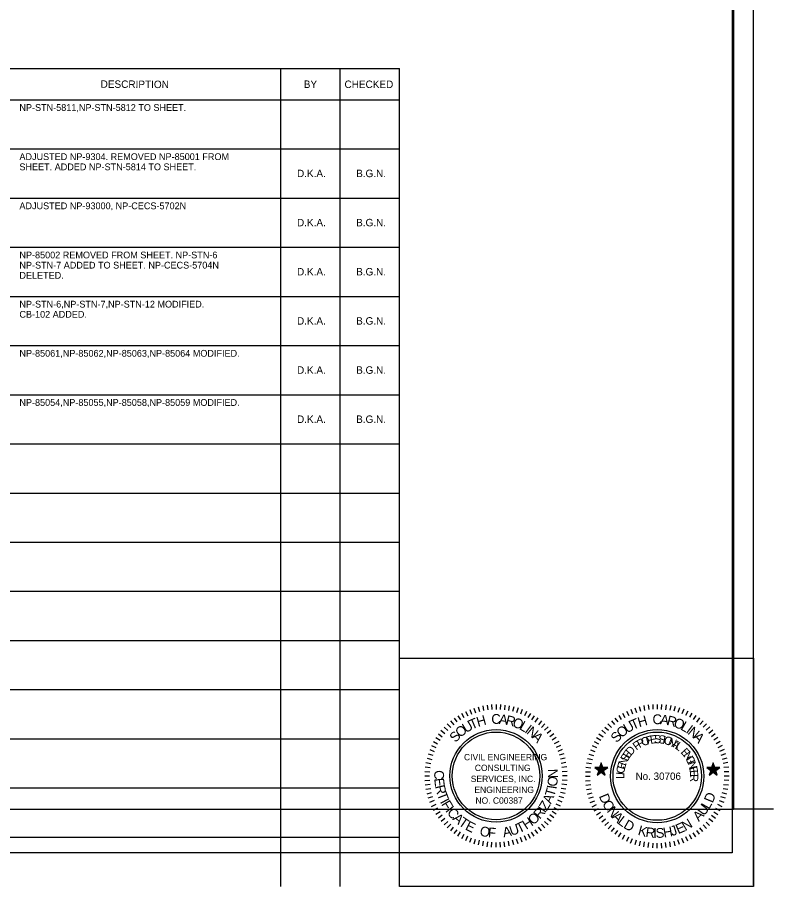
# Model space of a CAD drawing. Extents: x 260980 to 262786, y 322332 to 323393.
# Drawn here: x 262340 to 262786, y 322332 to 322845 of the extents above; entities that cross this region are included whole.
import ezdxf

# ---------------------------------------------------------------- set-up
doc = ezdxf.new("R2010")
doc.units = 0
for name, color, linetype in [('Level 1', 7, 'Continuous'), ('Level 2', 7, 'Continuous'), ('Level 23', 7, 'Continuous'), ('Level 3', 7, 'Continuous'), ('Level 5', 7, 'Continuous'), ('RD_SHT_SEAL_KA', 7, 'Continuous'), ('RD_SHT_TX', 7, 'Continuous')]:
    doc.layers.add(name, color=color, linetype=linetype)

msp = doc.modelspace()

# ---------------------------------------------------------------- linework, layer by layer
at = {"layer": 'Level 1'}
msp.add_lwpolyline([(262565.22, 322466.63), (262774.17, 322466.63), (262774.17, 322331.93), (262565.22, 322331.93)], close=True, dxfattribs=at)
at = {"layer": 'Level 2'}
msp.add_line((262761.95, 322377.79), (262785.98, 322377.79), dxfattribs=at)
at = {"layer": 'Level 23'}
msp.add_lwpolyline([(261111.06, 323336.45), (262761.54, 323336.45), (262761.54, 322351.79), (261111.06, 322351.79)], close=True, dxfattribs=at)
msp.add_lwpolyline([(261111.06, 323336.45), (262761.54, 323336.45), (262761.54, 322351.79), (261111.06, 322351.79)], close=True, dxfattribs=at)
at = {"layer": 'Level 3'}
msp.add_line((262774.17, 322332.83), (262774.17, 323381.93), dxfattribs=at)
at = {"layer": 'Level 5'}
msp.add_lwpolyline([(261111.06, 323310.45), (262762.33, 323310.45), (262762.33, 322377.34), (261111.06, 322377.34)], close=True, dxfattribs=at)
at = {"layer": 'RD_SHT_SEAL_KA'}
for p, q in [((262604.29, 322435.3), (262605.54, 322432.74)), ((262606.76, 322436.43), (262607.81, 322433.69)), ((262609.18, 322437.25), (262610.09, 322434.5)), ((262611.77, 322438.02), (262612.38, 322435.23)), ((262614.37, 322438.65), (262614.85, 322435.76)), ((262617.01, 322438.98), (262617.36, 322436.19)), ((262619.61, 322439.34), (262619.76, 322436.38)), ((262622.25, 322439.41), (262622.24, 322436.5)), ((262624.87, 322439.29), (262624.67, 322436.4)), ((262627.44, 322439.02), (262627.12, 322436.22)), ((262630.06, 322438.63), (262629.58, 322435.89)), ((262632.67, 322437.99), (262631.94, 322435.18)), ((262635.18, 322437.3), (262634.33, 322434.51)), ((262637.64, 322436.38), (262636.7, 322433.73)), ((262640.12, 322435.31), (262638.92, 322432.67)), ((262699.25, 322435.47), (262700.5, 322432.88)), ((262701.68, 322436.55), (262702.77, 322433.79)), ((262704.17, 322437.41), (262705.14, 322434.71)), ((262706.71, 322438.17), (262707.46, 322435.36)), ((262709.41, 322438.76), (262709.89, 322435.85)), ((262712.05, 322439.14), (262712.38, 322436.33)), ((262714.65, 322439.41), (262714.81, 322436.55)), ((262717.35, 322439.46), (262717.29, 322436.66)), ((262719.88, 322439.41), (262719.72, 322436.44)), ((262722.64, 322439.19), (262722.26, 322436.28)), ((262725.28, 322438.76), (262724.74, 322435.95)), ((262727.88, 322438.17), (262727.12, 322435.36)), ((262730.41, 322437.46), (262729.55, 322434.66)), ((262732.95, 322436.55), (262731.87, 322433.85)), ((262735.33, 322435.47), (262734.08, 322432.82)), ((262597.49, 322431.32), (262599.11, 322429.06)), ((262599.73, 322432.75), (262601.21, 322430.41)), ((262601.9, 322434.18), (262603.29, 322431.64)), ((262642.46, 322434.15), (262641.02, 322431.7)), ((262644.8, 322432.73), (262643.2, 322430.33)), ((262646.9, 322431.43), (262645.19, 322428.98)), ((262692.34, 322431.36), (262694.07, 322429.04)), ((262694.61, 322432.88), (262696.12, 322430.5)), ((262696.83, 322434.28), (262698.28, 322431.69)), ((262737.7, 322434.28), (262736.35, 322431.8)), ((262740.08, 322432.88), (262738.51, 322430.45)), ((262742.24, 322431.42), (262740.57, 322428.99)), ((262591.59, 322426.04), (262593.73, 322424.11)), ((262593.36, 322427.97), (262595.45, 322425.89)), ((262595.44, 322429.8), (262597.23, 322427.41)), ((262648.98, 322429.68), (262647.25, 322427.45)), ((262650.99, 322427.92), (262649.01, 322425.88)), ((262652.96, 322426.12), (262650.75, 322424.13)), ((262686.4, 322426.02), (262688.51, 322424.13)), ((262688.18, 322428.01), (262690.29, 322425.86)), ((262690.24, 322429.8), (262692.07, 322427.53)), ((262744.35, 322429.8), (262742.51, 322427.59)), ((262746.34, 322428.01), (262744.45, 322425.91)), ((262748.29, 322426.13), (262746.13, 322424.13)), ((262586.67, 322419.87), (262589.17, 322418.32)), ((262588.19, 322422), (262590.45, 322420.31)), ((262589.71, 322424.13), (262592.03, 322422.26)), ((262654.59, 322424.12), (262652.41, 322422.25)), ((262656.24, 322421.98), (262653.88, 322420.31)), ((262682.95, 322422.02), (262685.38, 322420.29)), ((262684.57, 322424.13), (262686.83, 322422.29)), ((262750.02, 322424.13), (262747.8, 322422.29)), ((262751.58, 322422.02), (262749.31, 322420.35)), ((262584.16, 322415.2), (262586.73, 322413.99)), ((262585.4, 322417.48), (262587.76, 322416.17)), ((262657.74, 322419.83), (262655.32, 322418.33)), ((262659.17, 322417.58), (262656.56, 322416.1)), ((262660.22, 322415.18), (262657.76, 322413.98)), ((262678.9, 322415.16), (262681.49, 322413.92)), ((262680.14, 322417.49), (262682.68, 322416.14)), ((262681.49, 322419.86), (262683.97, 322418.24)), ((262753.15, 322419.81), (262750.72, 322418.3)), ((262754.5, 322417.49), (262752.01, 322416.08)), ((262755.63, 322415.16), (262753.09, 322413.87)), ((262582.17, 322410.26), (262585, 322409.38)), ((262583.12, 322412.76), (262585.72, 322411.67)), ((262661.26, 322412.78), (262658.64, 322411.71)), ((262662.24, 322410.3), (262659.49, 322409.39)), ((262676.95, 322410.14), (262679.71, 322409.28)), ((262677.87, 322412.68), (262680.57, 322411.6)), ((262756.77, 322412.74), (262754.07, 322411.65)), ((262757.68, 322410.2), (262754.93, 322409.28)), ((262580.88, 322405.11), (262583.73, 322404.61)), ((262581.49, 322407.68), (262584.26, 322406.91)), ((262662.98, 322407.67), (262660.15, 322407.09)), ((262663.48, 322405.16), (262660.69, 322404.55)), ((262675.66, 322405.01), (262678.52, 322404.53)), ((262676.2, 322407.6), (262679.06, 322406.9)), ((262758.44, 322407.66), (262755.58, 322406.96)), ((262759.03, 322405.06), (262756.12, 322404.47)), ((262580.27, 322399.82), (262583.12, 322399.65)), ((262580.46, 322402.52), (262583.38, 322402.1)), ((262664.03, 322402.55), (262661.03, 322402.17)), ((262664.22, 322399.89), (262661.3, 322399.71)), ((262675.01, 322399.72), (262677.87, 322399.56)), ((262675.23, 322402.36), (262678.09, 322402.04)), ((262759.47, 322402.36), (262756.55, 322402.1)), ((262759.63, 322399.72), (262756.77, 322399.56)), ((262580.26, 322394.6), (262583.13, 322394.81)), ((262580.29, 322397.29), (262583.05, 322397.26)), ((262664.21, 322394.6), (262661.32, 322394.8)), ((262664.2, 322397.32), (262661.45, 322397.27)), ((262674.95, 322397.07), (262677.82, 322397.07)), ((262674.95, 322394.43), (262677.82, 322394.59)), ((262759.63, 322394.48), (262756.77, 322394.64)), ((262759.73, 322397.07), (262756.87, 322397.13)), ((262580.5, 322392.02), (262583.37, 322392.31)), ((262580.83, 322389.38), (262583.68, 322389.89)), ((262663.49, 322389.33), (262660.66, 322389.87)), ((262663.97, 322392), (262661.03, 322392.3)), ((262675.23, 322391.73), (262678.14, 322392.16)), ((262675.6, 322389.14), (262678.41, 322389.62)), ((262759.03, 322389.14), (262756.12, 322389.68)), ((262759.36, 322391.78), (262756.5, 322392.05)), ((262581.5, 322386.75), (262584.2, 322387.49)), ((262582.25, 322384.31), (262584.94, 322385.13)), ((262662.22, 322384.29), (262659.43, 322385.14)), ((262662.98, 322386.81), (262660.17, 322387.54)), ((262676.25, 322386.49), (262679, 322387.19)), ((262677.01, 322384.01), (262679.71, 322384.87)), ((262757.63, 322384.01), (262754.93, 322384.87)), ((262758.44, 322386.54), (262755.58, 322387.3)), ((262583.09, 322381.73), (262585.82, 322382.86)), ((262584.15, 322379.26), (262586.85, 322380.6)), ((262660.26, 322379.39), (262657.73, 322380.57)), ((262661.3, 322381.83), (262658.64, 322382.84)), ((262677.82, 322381.47), (262680.57, 322382.49)), ((262678.95, 322378.99), (262681.54, 322380.28)), ((262755.68, 322378.99), (262753.09, 322380.28)), ((262756.77, 322381.52), (262754.01, 322382.55)), ((262585.41, 322376.96), (262587.83, 322378.45)), ((262586.73, 322374.74), (262589.18, 322376.27)), ((262588.24, 322372.43), (262590.44, 322374.23)), ((262656.22, 322372.41), (262653.91, 322374.2)), ((262657.77, 322374.58), (262655.26, 322376.2)), ((262659.04, 322376.97), (262656.48, 322378.36)), ((262680.08, 322376.61), (262682.68, 322378.06)), ((262681.54, 322374.34), (262683.87, 322375.85)), ((262683, 322372.13), (262685.32, 322373.85)), ((262751.63, 322372.13), (262749.31, 322373.8)), ((262753.15, 322374.29), (262750.72, 322375.8)), ((262754.5, 322376.66), (262751.96, 322378.01)), ((262589.76, 322370.46), (262591.99, 322372.23)), ((262591.57, 322368.45), (262593.75, 322370.4)), ((262593.44, 322366.6), (262595.45, 322368.68)), ((262651.03, 322366.58), (262648.97, 322368.71)), ((262652.88, 322368.45), (262650.81, 322370.39)), ((262654.68, 322370.43), (262652.41, 322372.19)), ((262684.62, 322370.07), (262686.89, 322371.86)), ((262686.4, 322368.02), (262688.51, 322370.02)), ((262748.23, 322368.02), (262746.18, 322370.02)), ((262750.07, 322370.07), (262747.8, 322371.91)), ((262595.46, 322364.77), (262597.19, 322367)), ((262597.51, 322363.24), (262599.2, 322365.5)), ((262599.64, 322361.72), (262601.2, 322364.15)), ((262644.7, 322361.77), (262643.22, 322364.11)), ((262646.9, 322363.23), (262645.25, 322365.45)), ((262648.95, 322364.76), (262647.25, 322367)), ((262688.35, 322366.08), (262690.24, 322368.24)), ((262690.29, 322364.4), (262692.07, 322366.56)), ((262692.4, 322362.79), (262694.13, 322365.05)), ((262694.56, 322361.22), (262696.12, 322363.7)), ((262740.03, 322361.22), (262738.51, 322363.65)), ((262742.29, 322362.79), (262740.62, 322365.11)), ((262744.29, 322364.35), (262742.51, 322366.56)), ((262746.4, 322366.13), (262744.4, 322368.29)), ((262601.97, 322360.37), (262603.34, 322362.81)), ((262604.32, 322359.14), (262605.51, 322361.85)), ((262606.72, 322358.13), (262607.81, 322360.73)), ((262609.22, 322357.18), (262610.07, 322359.97)), ((262611.8, 322356.5), (262612.38, 322359.29)), ((262614.33, 322355.92), (262614.83, 322358.77)), ((262616.93, 322355.42), (262617.34, 322358.34)), ((262627.43, 322355.47), (262627.1, 322358.37)), ((262630.02, 322355.91), (262629.59, 322358.68)), ((262632.66, 322356.5), (262631.98, 322359.28)), ((262635.18, 322357.19), (262634.32, 322359.91)), ((262637.71, 322358.14), (262636.63, 322360.83)), ((262640.18, 322359.19), (262638.92, 322361.83)), ((262642.49, 322360.37), (262641.14, 322362.81)), ((262696.88, 322359.92), (262698.28, 322362.41)), ((262699.31, 322358.68), (262700.5, 322361.33)), ((262701.63, 322357.6), (262702.82, 322360.3)), ((262704.22, 322356.74), (262705.03, 322359.49)), ((262706.76, 322355.93), (262707.41, 322358.79)), ((262727.88, 322355.98), (262727.23, 322358.79)), ((262730.41, 322356.74), (262729.55, 322359.44)), ((262732.95, 322357.6), (262731.87, 322360.3)), ((262735.43, 322358.74), (262734.19, 322361.33)), ((262737.7, 322359.92), (262736.35, 322362.41)), ((262619.63, 322355.24), (262619.79, 322358.17)), ((262622.25, 322355.2), (262622.23, 322357.99)), ((262624.92, 322355.23), (262624.74, 322358.15)), ((262709.35, 322355.39), (262709.89, 322358.3)), ((262712, 322355.01), (262712.38, 322357.87)), ((262714.7, 322354.74), (262714.86, 322357.6)), ((262717.35, 322354.69), (262717.35, 322357.55)), ((262719.99, 322354.63), (262719.83, 322357.65)), ((262722.58, 322355.01), (262722.26, 322357.87)), ((262725.23, 322355.39), (262724.74, 322358.25))]:
    msp.add_line(p, q, dxfattribs=at)
for points in [[(262684.24, 322405.01), (262683.33, 322402.15), (262680.41, 322402.15), (262682.78, 322400.37), (262681.81, 322397.67), (262684.3, 322399.4), (262686.62, 322397.67), (262685.7, 322400.42), (262688.08, 322402.2), (262685.16, 322402.2)], [(262684.19, 322404.58), (262683.43, 322402.1), (262680.73, 322402.1), (262682.84, 322400.48), (262682.08, 322397.94), (262684.19, 322399.56), (262686.35, 322397.94), (262685.54, 322400.53), (262687.75, 322402.04), (262685.11, 322402.1)], [(262750.39, 322405.01), (262749.42, 322402.2), (262746.56, 322402.15), (262748.93, 322400.42), (262747.96, 322397.61), (262750.39, 322399.4), (262752.77, 322397.61), (262751.8, 322400.42), (262754.23, 322402.2), (262751.26, 322402.2)], [(262750.34, 322404.64), (262749.53, 322402.1), (262746.88, 322402.04), (262749.1, 322400.42), (262748.29, 322397.94), (262750.39, 322399.45), (262752.55, 322397.94), (262751.74, 322400.48), (262753.9, 322402.1), (262751.2, 322402.04)], [(262684.3, 322404.2), (262683.43, 322401.94), (262681.11, 322401.94), (262683.05, 322400.53), (262682.35, 322398.26), (262684.24, 322399.66), (262686.19, 322398.21), (262685.38, 322400.59), (262687.38, 322401.88), (262685, 322401.94)], [(262684.3, 322403.82), (262683.54, 322401.83), (262681.49, 322401.77), (262683.22, 322400.59), (262682.57, 322398.59), (262684.19, 322399.83), (262685.97, 322398.59), (262685.38, 322400.59), (262687, 322401.88), (262684.89, 322401.77)], [(262684.24, 322403.45), (262683.7, 322401.72), (262681.87, 322401.66), (262683.33, 322400.64), (262682.73, 322398.86), (262684.24, 322399.99), (262685.75, 322398.86), (262685.16, 322400.64), (262686.57, 322401.72), (262684.89, 322401.72)], [(262684.24, 322403.07), (262683.81, 322401.56), (262682.25, 322401.61), (262683.49, 322400.69), (262683, 322399.24), (262684.3, 322400.15), (262685.54, 322399.18), (262685, 322400.69), (262686.3, 322401.5), (262684.73, 322401.56)], [(262684.24, 322402.64), (262683.87, 322401.5), (262682.62, 322401.34), (262683.65, 322400.75), (262683.27, 322399.56), (262684.19, 322400.26), (262685.32, 322399.5), (262684.95, 322400.75), (262685.86, 322401.45), (262684.62, 322401.45)], [(262684.24, 322402.26), (262683.97, 322401.34), (262683, 322401.34), (262683.81, 322400.8), (262683.49, 322399.88), (262684.24, 322400.37), (262685.05, 322399.83), (262684.78, 322400.75), (262685.54, 322401.29), (262684.51, 322401.39)], [(262684.24, 322401.83), (262684.03, 322401.23), (262683.33, 322401.23), (262683.87, 322400.8), (262683.76, 322400.21), (262684.3, 322400.59), (262684.73, 322400.15), (262684.62, 322400.8), (262685.16, 322401.18), (262684.46, 322401.23)], [(262684.3, 322401.5), (262684.08, 322401.12), (262683.76, 322401.12), (262684.08, 322400.85), (262683.92, 322400.48), (262684.3, 322400.75), (262684.51, 322400.48), (262684.4, 322400.91), (262684.73, 322401.07), (262684.4, 322401.07)], [(262684.3, 322401.07), (262684.24, 322400.91), (262684.03, 322400.96), (262684.19, 322400.96), (262684.13, 322400.8), (262684.24, 322400.8), (262684.3, 322400.8), (262684.3, 322400.91), (262684.46, 322401.01), (262684.3, 322401.01)], [(262750.39, 322404.2), (262749.69, 322401.88), (262747.26, 322401.94), (262749.2, 322400.53), (262748.5, 322398.21), (262750.39, 322399.66), (262752.34, 322398.26), (262751.58, 322400.48), (262753.53, 322401.99), (262751.15, 322401.94)], [(262750.34, 322403.82), (262749.75, 322401.77), (262747.64, 322401.77), (262749.42, 322400.59), (262748.61, 322398.64), (262750.39, 322399.83), (262752.07, 322398.64), (262751.42, 322400.59), (262753.15, 322401.83), (262751.04, 322401.83)], [(262750.34, 322403.39), (262749.8, 322401.66), (262747.96, 322401.72), (262749.42, 322400.69), (262748.93, 322398.86), (262750.34, 322399.94), (262751.8, 322398.91), (262751.31, 322400.59), (262752.82, 322401.66), (262750.93, 322401.72)], [(262750.45, 322403.01), (262749.91, 322401.61), (262748.34, 322401.61), (262749.64, 322400.75), (262749.1, 322399.18), (262750.39, 322400.1), (262751.58, 322399.24), (262751.2, 322400.64), (262752.34, 322401.56), (262750.88, 322401.61)], [(262750.39, 322402.64), (262749.96, 322401.5), (262748.72, 322401.45), (262749.8, 322400.69), (262749.37, 322399.56), (262750.39, 322400.31), (262751.37, 322399.5), (262750.99, 322400.75), (262752.07, 322401.45), (262750.77, 322401.5)], [(262750.39, 322402.2), (262750.12, 322401.34), (262749.1, 322401.34), (262749.91, 322400.75), (262749.58, 322399.88), (262750.39, 322400.37), (262751.15, 322399.83), (262750.88, 322400.75), (262751.58, 322401.34), (262750.66, 322401.34)], [(262750.39, 322401.88), (262750.07, 322401.23), (262749.53, 322401.18), (262750.02, 322400.85), (262749.8, 322400.21), (262750.39, 322400.53), (262750.93, 322400.15), (262750.72, 322400.75), (262751.31, 322401.18), (262750.66, 322401.23)], [(262750.34, 322401.5), (262750.28, 322401.12), (262749.85, 322401.12), (262750.23, 322400.85), (262750.02, 322400.48), (262750.45, 322400.69), (262750.72, 322400.48), (262750.55, 322400.8), (262750.93, 322401.12), (262750.55, 322401.07)], [(262750.45, 322401.07), (262750.39, 322400.96), (262750.23, 322400.96), (262750.28, 322400.91), (262750.28, 322400.75), (262750.34, 322400.85), (262750.5, 322400.85), (262750.45, 322400.91), (262750.5, 322400.96), (262750.39, 322400.91)]]:
    msp.add_lwpolyline(points, close=True, dxfattribs=at)
for radius in [27.48, 26.04]:
    msp.add_circle((262717.31, 322397.08), radius, dxfattribs=at)
for major_axis in [(0.01, 27.28), (0.01, 25.84)]:
    msp.add_ellipse((262622.22, 322397.26), major_axis=major_axis, ratio=0.998589, dxfattribs=at)
at = {"layer": 'RD_SHT_TX'}
for p, q in [((262254.62, 322814.63), (262565.22, 322814.63)), ((262495.22, 322331.93), (262495.22, 322814.63)), ((262530.22, 322331.93), (262530.22, 322814.63)), ((262565.22, 322331.93), (262565.22, 322814.63)), ((262565.22, 322795.93), (261944.02, 322795.93)), ((262565.22, 322766.93), (261944.02, 322766.93)), ((262565.22, 322737.93), (261944.02, 322737.93)), ((262565.22, 322708.93), (261944.02, 322708.93)), ((262565.22, 322679.93), (261944.02, 322679.93)), ((262565.22, 322650.93), (261944.02, 322650.93)), ((262565.22, 322621.93), (261944.02, 322621.93)), ((262565.22, 322592.93), (261944.02, 322592.93)), ((262565.22, 322563.93), (261944.02, 322563.93)), ((262565.22, 322534.93), (261944.02, 322534.93)), ((262565.22, 322505.93), (261944.02, 322505.93)), ((262565.22, 322476.93), (261944.02, 322476.93)), ((262565.22, 322447.93), (261944.02, 322447.93)), ((262565.22, 322418.93), (261944.02, 322418.93)), ((262565.22, 322389.93), (261944.02, 322389.93)), ((262565.22, 322360.93), (261944.02, 322360.93))]:
    msp.add_line(p, q, dxfattribs=at)

# ---------------------------------------------------------------- texts
at = {"layer": 'RD_SHT_SEAL_KA'}
for s, height, rotation, p in [('T', 5.79, 23.2887, (262607.89, 322424.49)), ('H', 5.79, 15.7743, (262611.58, 322426.13)), ('C', 5.79, 0.6858, (262619.46, 322427.9)), ('A', 5.79, 352.8136, (262623.68, 322427.99)), ('R', 5.79, 345.657, (262627.5, 322427.57)), ('O', 5.79, 338.1426, (262631.42, 322426.62)), ('T', 5.79, 23.2887, (262702.99, 322424.31)), ('H', 5.79, 15.7743, (262706.67, 322425.95)), ('C', 5.79, 0.6858, (262714.55, 322427.72)), ('A', 5.79, 352.8136, (262718.78, 322427.81)), ('R', 5.79, 345.657, (262722.59, 322427.39)), ('O', 5.79, 338.1426, (262726.51, 322426.44)), ('O', 5.79, 39.0332, (262601.04, 322419.58)), ('U', 5.79, 30.8031, (262604.45, 322422.38)), ('L', 5.79, 329.9125, (262635.52, 322425)), ('I', 5.79, 323.1138, (262638.71, 322423.23)), ('N', 5.79, 320.609, (262639.83, 322422.48)), ('O', 5.79, 39.0332, (262696.14, 322419.4)), ('U', 5.79, 30.8031, (262699.55, 322422.2)), ('L', 5.79, 329.9125, (262730.62, 322424.82)), ('I', 5.79, 323.1138, (262733.81, 322423.05)), ('N', 5.79, 320.609, (262734.93, 322422.3)), ('S', 5.79, 46.5476, (262598.3, 322416.62)), ('A', 5.79, 313.0946, (262642.98, 322419.96)), ('S', 5.79, 46.5476, (262693.4, 322416.44)), ('O', 4.82, 21.7793, (262708.87, 322414.62)), ('F', 4.82, 14.3582, (262711.21, 322415.56)), ('E', 4.82, 7.9051, (262713.32, 322416.13)), ('S', 4.82, 1.452, (262715.49, 322416.45)), ('S', 4.82, 354.6762, (262717.79, 322416.53)), ('I', 4.82, 347.9004, (262720.08, 322416.33)), ('O', 4.82, 345.6418, (262720.84, 322416.2)), ('A', 5.79, 313.0946, (262738.08, 322419.78)), ('P', 4.82, 35.3308, (262704.99, 322412.16)), ('R', 4.82, 28.555, (262706.86, 322413.51)), ('N', 4.82, 338.2207, (262723.28, 322415.58)), ('A', 4.82, 331.445, (262725.42, 322414.75)), ('L', 4.82, 324.9919, (262727.36, 322413.72)), ('CIVIL ENGINEERING', 3.7513, 359.9897, (262603.32, 322406.46)), ('S', 4.82, 62.165, (262699.5, 322404.99)), ('E', 4.82, 55.3892, (262700.56, 322407.03)), ('D', 4.82, 48.9361, (262701.78, 322408.85)), ('E', 4.82, 312.0319, (262730.83, 322411.04)), ('N', 4.82, 305.5788, (262732.32, 322409.42)), ('E', 4.82, 75.3939, (262698.16, 322400.71)), ('N', 4.82, 68.9407, (262698.69, 322402.84)), ('G', 4.82, 298.803, (262733.67, 322407.56)), ('I', 4.82, 291.7046, (262734.84, 322405.46)), ('N', 4.82, 289.446, (262735.16, 322404.76)), ('C', 5.79, 268.515, (262585.83, 322400.71)), ('CONSULTING', 3.751, 359.9897, (262609.7, 322400.11)), ('N', 5.79, 91.8428, (262658.74, 322395.93)), ('C', 4.82, 82.4923, (262697.86, 322398.32)), ('E', 4.82, 282.6702, (262735.94, 322402.59)), ('E', 4.82, 276.2171, (262736.44, 322400.46)), ('E', 5.79, 276.3872, (262585.7, 322395.7)), ('SERVICES, INC.', 3.7513, 359.9897, (262607.31, 322393.62)), ('O', 5.79, 83.6128, (262658.17, 322390.72)), ('L', 4.82, 90.8813, (262697.88, 322395.47)), ('I', 4.82, 84.7509, (262697.82, 322397.55)), ('R', 4.82, 269.764, (262736.7, 322398.29)), ('R', 5.79, 283.5438, (262586.18, 322391.16)), ('ENGINEERING', 3.7513, 359.9897, (262609.45, 322387.19)), ('T', 5.79, 73.5935, (262656.48, 322384.56)), ('I', 5.79, 81.108, (262657.85, 322389.15)), ('T', 5.79, 291.0582, (262587.29, 322386.5)), ('I', 5.79, 298.5727, (262589, 322382.02)), ('NO. C00387', 3.751, 359.9897, (262610.06, 322380.82)), ('A', 5.79, 66.437, (262654.63, 322380.39)), ('D', 5.78, 292.563, (262682.8, 322385.32)), ('D', 5.78, 67.437, (262749.99, 322380.91)), ('F', 5.79, 301.0775, (262589.7, 322380.59)), ('I', 5.79, 308.234, (262592.03, 322376.67)), ('I', 5.79, 56.4177, (262651.2, 322375.01)), ('Z', 5.79, 58.9225, (262652.15, 322376.3)), ('O', 5.78, 300.0892, (262684.64, 322380.91)), ('N', 5.78, 308.3321, (262687.29, 322376.39)), ('U', 5.78, 53.1014, (262744.97, 322373.32)), ('L', 5.78, 60.6276, (262747.84, 322377.15)), ('C', 5.79, 310.7388, (262592.96, 322375.37)), ('A', 5.79, 318.6111, (262596.23, 322371.57)), ('O', 5.79, 40.6733, (262644.08, 322367.98)), ('R', 5.79, 48.9033, (262648.04, 322371.41)), ('A', 5.78, 315.8583, (262690.26, 322372.63)), ('A', 5.78, 45.9336, (262741.79, 322370.06)), ('T', 5.79, 325.7677, (262599.64, 322368.53)), ('E', 5.79, 333.2821, (262603.59, 322365.82)), ('U', 5.79, 18.13, (262631.18, 322361.83)), ('T', 5.79, 25.6444, (262635.74, 322363.31)), ('H', 5.79, 33.1588, (262640.06, 322365.37)), ('L', 5.78, 323.0261, (262693.52, 322369.45)), ('D', 5.78, 329.8355, (262696.96, 322366.82)), ('E', 5.78, 23.6537, (262729.72, 322362.8)), ('N', 5.78, 30.8215, (262733.9, 322364.61)), ('O', 5.79, 348.0127, (262612.19, 322362.12)), ('F', 5.79, 356.2428, (262617.33, 322361.05)), ('A', 5.79, 10.9734, (262626.7, 322360.99)), ('K', 5.78, 344.9476, (262705.56, 322362.57)), ('R', 5.78, 352.4738, (262710.18, 322361.32)), ('I', 5.78, 360, (262714.92, 322360.7)), ('S', 5.78, 2.5087, (262716.52, 322360.63)), ('H', 5.78, 10.0349, (262721.3, 322360.84)), ('J', 5.78, 17.5611, (262726.01, 322361.67))]:
    msp.add_text(s, height=height, rotation=rotation, dxfattribs=at).set_placement(p)
msp.add_text('No. 30706', height=4.336, dxfattribs=at).set_placement((262704.54, 322394.9))
at = {"layer": 'RD_SHT_TX'}
for s, height, rotation, p in [('DESCRIPTION', 4.4083, 359.7246, (262388.92, 322803.17)), ('BY', 4.408, 359.7246, (262508.77, 322803.09)), ('NP-STN-5811,NP-STN-5812 TO SHEET.', 4, 360, (262341.03, 322789.54)), ('ADJUSTED NP-9304. REMOVED NP-85001 FROM', 4, 360, (262341.03, 322760.54)), ('SHEET. ADDED NP-STN-5814 TO SHEET.', 4, 360, (262341.03, 322754.54)), ('D.K.A.', 4.4, 360, (262504.81, 322750.46)), ('B.G.N.', 4.4, 360, (262539.68, 322750.46)), ('ADJUSTED NP-93000, NP-CECS-5702N', 4, 360, (262341.03, 322731.54)), ('D.K.A.', 4.4, 360, (262504.81, 322721.46)), ('B.G.N.', 4.4, 360, (262539.68, 322721.46)), ('NP-85002 REMOVED FROM SHEET. NP-STN-6', 4, 360, (262341.03, 322702.54)), ('NP-STN-7 ADDED TO SHEET. NP-CECS-5704N', 4, 360, (262341.03, 322696.54)), ('D.K.A.', 4.4, 360, (262504.81, 322692.46)), ('B.G.N.', 4.4, 360, (262539.68, 322692.46)), ('DELETED.', 4, 360, (262341.03, 322690.54)), ('NP-STN-6,NP-STN-7,NP-STN-12 MODIFIED. ', 4, 360, (262341.03, 322673.54)), ('CB-102 ADDED.', 4, 360, (262341.03, 322667.54)), ('D.K.A.', 4.4, 360, (262504.81, 322663.46)), ('B.G.N.', 4.4, 360, (262539.68, 322663.46)), ('NP-85061,NP-85062,NP-85063,NP-85064 MODIFIED.', 4, 360, (262341.03, 322644.54)), ('D.K.A.', 4.4, 360, (262504.81, 322634.46)), ('B.G.N.', 4.4, 360, (262539.68, 322634.46)), ('NP-85054,NP-85055,NP-85058,NP-85059 MODIFIED.', 4, 360, (262341.03, 322615.54)), ('D.K.A.', 4.4, 360, (262504.81, 322605.46)), ('B.G.N.', 4.4, 360, (262539.68, 322605.46))]:
    msp.add_text(s, height=height, rotation=rotation, dxfattribs=at).set_placement(p)
msp.add_text('CHECKED', height=4.4, dxfattribs=at).set_placement((262532.82, 322803.05))

doc.saveas('drawing.dxf')
